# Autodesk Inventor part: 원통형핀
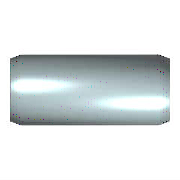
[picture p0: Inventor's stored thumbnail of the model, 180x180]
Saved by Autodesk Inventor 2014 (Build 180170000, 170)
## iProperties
IsCustomPart: 1
Created: 2012-02
Part Number: 원통형핀
Material: 강철, 연강
Description: 평행 핀
Document SubType Name: Modeling
Standard: KS B 1320
Designer: mduedu
Standards Organization: KS
Language: ko-KR
Size Designation: B 2 x  14
Categories: <MemberInstance><Categories><Category DisplayName="조임쇠" InternalName="e4da775c-781d-43d5-af7c-5136215cf5a6" Mnemonic="FSTN"><Category DisplayName="핀" InternalNa
Density: 1 g/cm^3
Appearance: 파란색 - 벽 페인트 - 광택
Author: mduedu
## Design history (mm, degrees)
sketch "스케치"
  geometry: C1 r 1 at (0, 0); 1 further point
  constraints: 1 centre point, 1 coincident
  dimensions: "d1" = 2 diameter of C1 (= NND)
extrude "본체" new body sketch "스케치" distance "d2" = 14 (= NLG); taper "d3" = 0 deg
chamfer "스케치2" distance "d8" = 0.35 (= PHH); stored, may be unused: angle "d9" = 15 deg (= FAWI), second distance "d12" = 0.35 (= PHH)
node "작업 평면1"
node "작업 평면2"
node "작업 평면3"
body "Solid1"
chamfer "모따기1" distance "d4" = 0.35 (= PHH); stored, may be unused: angle "d5" = 15 deg (= FAWI), second distance "d11" = 0.35 (= PHH)
other parameters: "NND" = 2 [user parameter; used in 1 equation term], "NLG" = 14 [user parameter; used in 1 equation term], "PHH" = 0.35 [user parameter; used in 4 equation terms], "FAWI" = 15 deg [user parameter; used in 2 equation terms], "d13" = 0, "d15" = 0, "d16" = 0, "KAH" = 0.25 [user parameter]
